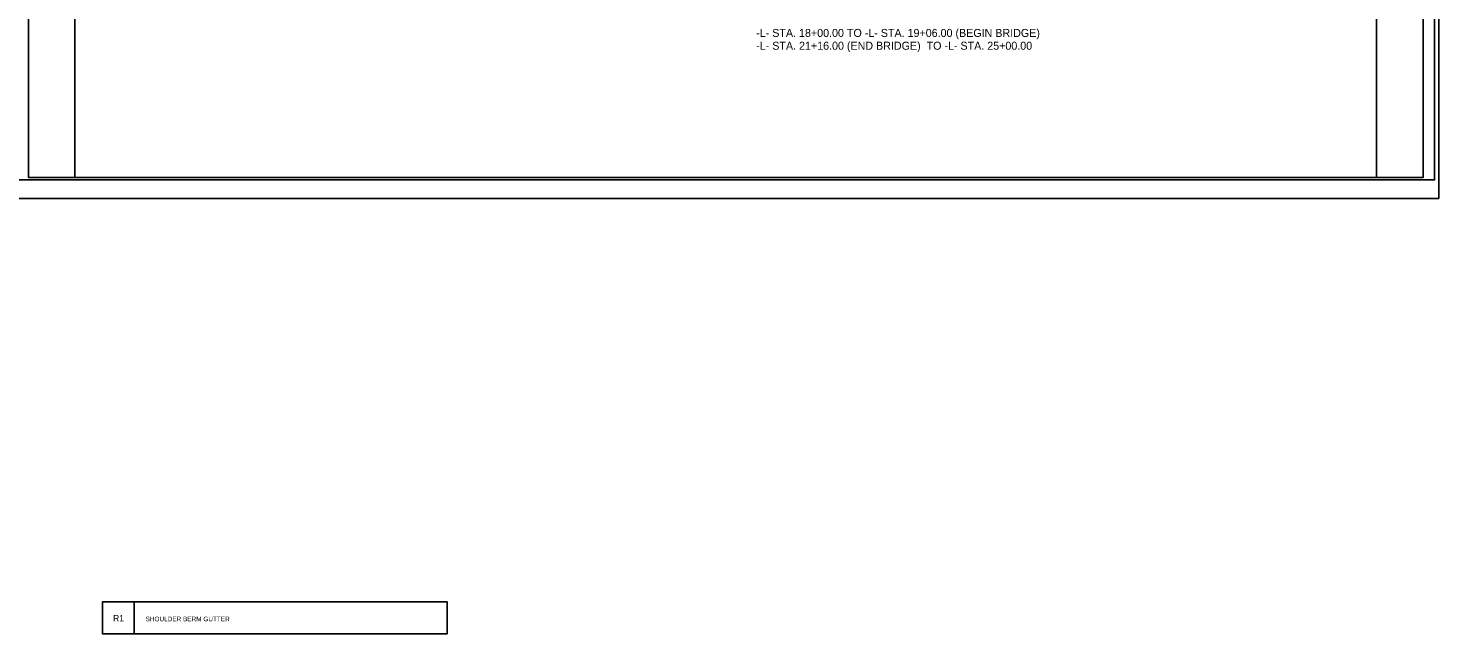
# Model space of a CAD drawing. Extents: x 1593595 to 1594166, y 741647 to 741854.
# Drawn here: x 1593959.3 to 1594141.4, y 741646.7 to 741724.8 of the extents above; entities that cross this region are included whole.
import ezdxf

# ---------------------------------------------------------------- set-up
doc = ezdxf.new("R2010")
doc.units = 0
for name, color, linetype in [('Prop Dimension', 7, 'Continuous'), ('Prop Pavement Schedule Description CELL', 7, 'Continuous'), ('Sheet Clip Boundary CELL', 7, 'Continuous'), ('Sheet Cutting Line CELL', 7, 'Continuous'), ('Sheet Layout Plan Border', 7, 'Continuous'), ('Sheet Plan CELL', 7, 'Continuous'), ('Sheet Plan Layout CELL', 7, 'Continuous'), ('Sheet Plot Border Inside CELL', 7, 'Continuous'), ('Sheet Plot Border Outside CELL', 7, 'Continuous')]:
    doc.layers.add(name, color=color, linetype=linetype)

msp = doc.modelspace()

# ---------------------------------------------------------------- linework, layer by layer
at = {"layer": 'Prop Pavement Schedule Description CELL'}
msp.add_lwpolyline([(1593972.97, 741646.7), (1593968.87, 741646.7), (1593968.87, 741650.8), (1594013.36, 741650.8), (1594013.36, 741646.7), (1593972.97, 741646.7), (1593972.97, 741650.8)], dxfattribs=at)
at = {"layer": 'Sheet Clip Boundary CELL'}
msp.add_lwpolyline([(1593965.32, 741705.56), (1594133.32, 741705.56), (1594133.32, 741806.18), (1594110.61, 741806.18), (1594110.61, 741831.56), (1593965.32, 741831.56)], close=True, dxfattribs=at)
at = {"layer": 'Sheet Cutting Line CELL'}
msp.add_line((1593939.34, 741702.86), (1594141.36, 741702.86), dxfattribs=at)
at = {"layer": 'Sheet Layout Plan Border'}
msp.add_lwpolyline([(1593965.32, 741705.56), (1594133.32, 741705.56), (1594133.32, 741806.18), (1594110.61, 741806.18), (1594110.61, 741831.56), (1593965.32, 741831.56)], close=True, dxfattribs=at)
at = {"layer": 'Sheet Plan CELL'}
msp.add_line((1593959.32, 741705.56), (1593959.32, 741705.56), dxfattribs=at)
for points in [[(1593959.32, 741705.56), (1593959.31, 741831.56), (1594115.31, 741831.56), (1594115.31, 741813.55), (1594139.32, 741813.55), (1594139.32, 741705.56)], [(1594139.32, 741831.56), (1593959.32, 741831.56), (1593959.32, 741705.56), (1594139.32, 741705.56)]]:
    msp.add_lwpolyline(points, close=True, dxfattribs=at)
at = {"layer": 'Sheet Plan Layout CELL'}
msp.add_lwpolyline([(1593959.31, 741831.56), (1593959.32, 741705.56), (1594139.32, 741705.56), (1594139.32, 741806.18), (1594110.61, 741806.18), (1594110.61, 741831.56)], close=True, dxfattribs=at)
at = {"layer": 'Sheet Plot Border Inside CELL'}
msp.add_lwpolyline([(1593940.9, 741705.26), (1594140.82, 741705.26), (1594140.82, 741831.86), (1593940.9, 741831.86)], close=True, dxfattribs=at)
at = {"layer": 'Sheet Plot Border Outside CELL'}
msp.add_lwpolyline([(1593939.34, 741702.86), (1594141.36, 741702.86), (1594141.36, 741834.26), (1593939.34, 741834.26)], close=True, dxfattribs=at)

# ---------------------------------------------------------------- texts
at = {"layer": 'Prop Dimension'}
for s, p in [('-L- STA. 18+00.00 TO -L- STA. 19+06.00 (BEGIN BRIDGE)', (1594053.25, 741723.7)), ('-L- STA. 21+16.00 (END BRIDGE)  TO -L- STA. 25+00.00', (1594053.25, 741722.05))]:
    msp.add_text(s, height=1.033, dxfattribs=at).set_placement(p)
at = {"layer": 'Prop Pavement Schedule Description CELL'}
for s, height, p in [('R1', 0.819, (1593970.24, 741648.3)), ('SHOULDER BERM GUTTER', 0.6, (1593974.43, 741648.31))]:
    msp.add_text(s, height=height, dxfattribs=at).set_placement(p)

doc.saveas('drawing.dxf')
